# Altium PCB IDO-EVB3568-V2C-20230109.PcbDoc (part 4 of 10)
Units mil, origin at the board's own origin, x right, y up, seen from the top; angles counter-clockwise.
Board outline 5318 x 3544 mil, 2 copper layers (TOP, BOTTOM), stack 6.8 mil thick; 790 components, 626 nets, 2890 pads, 1922 vias.
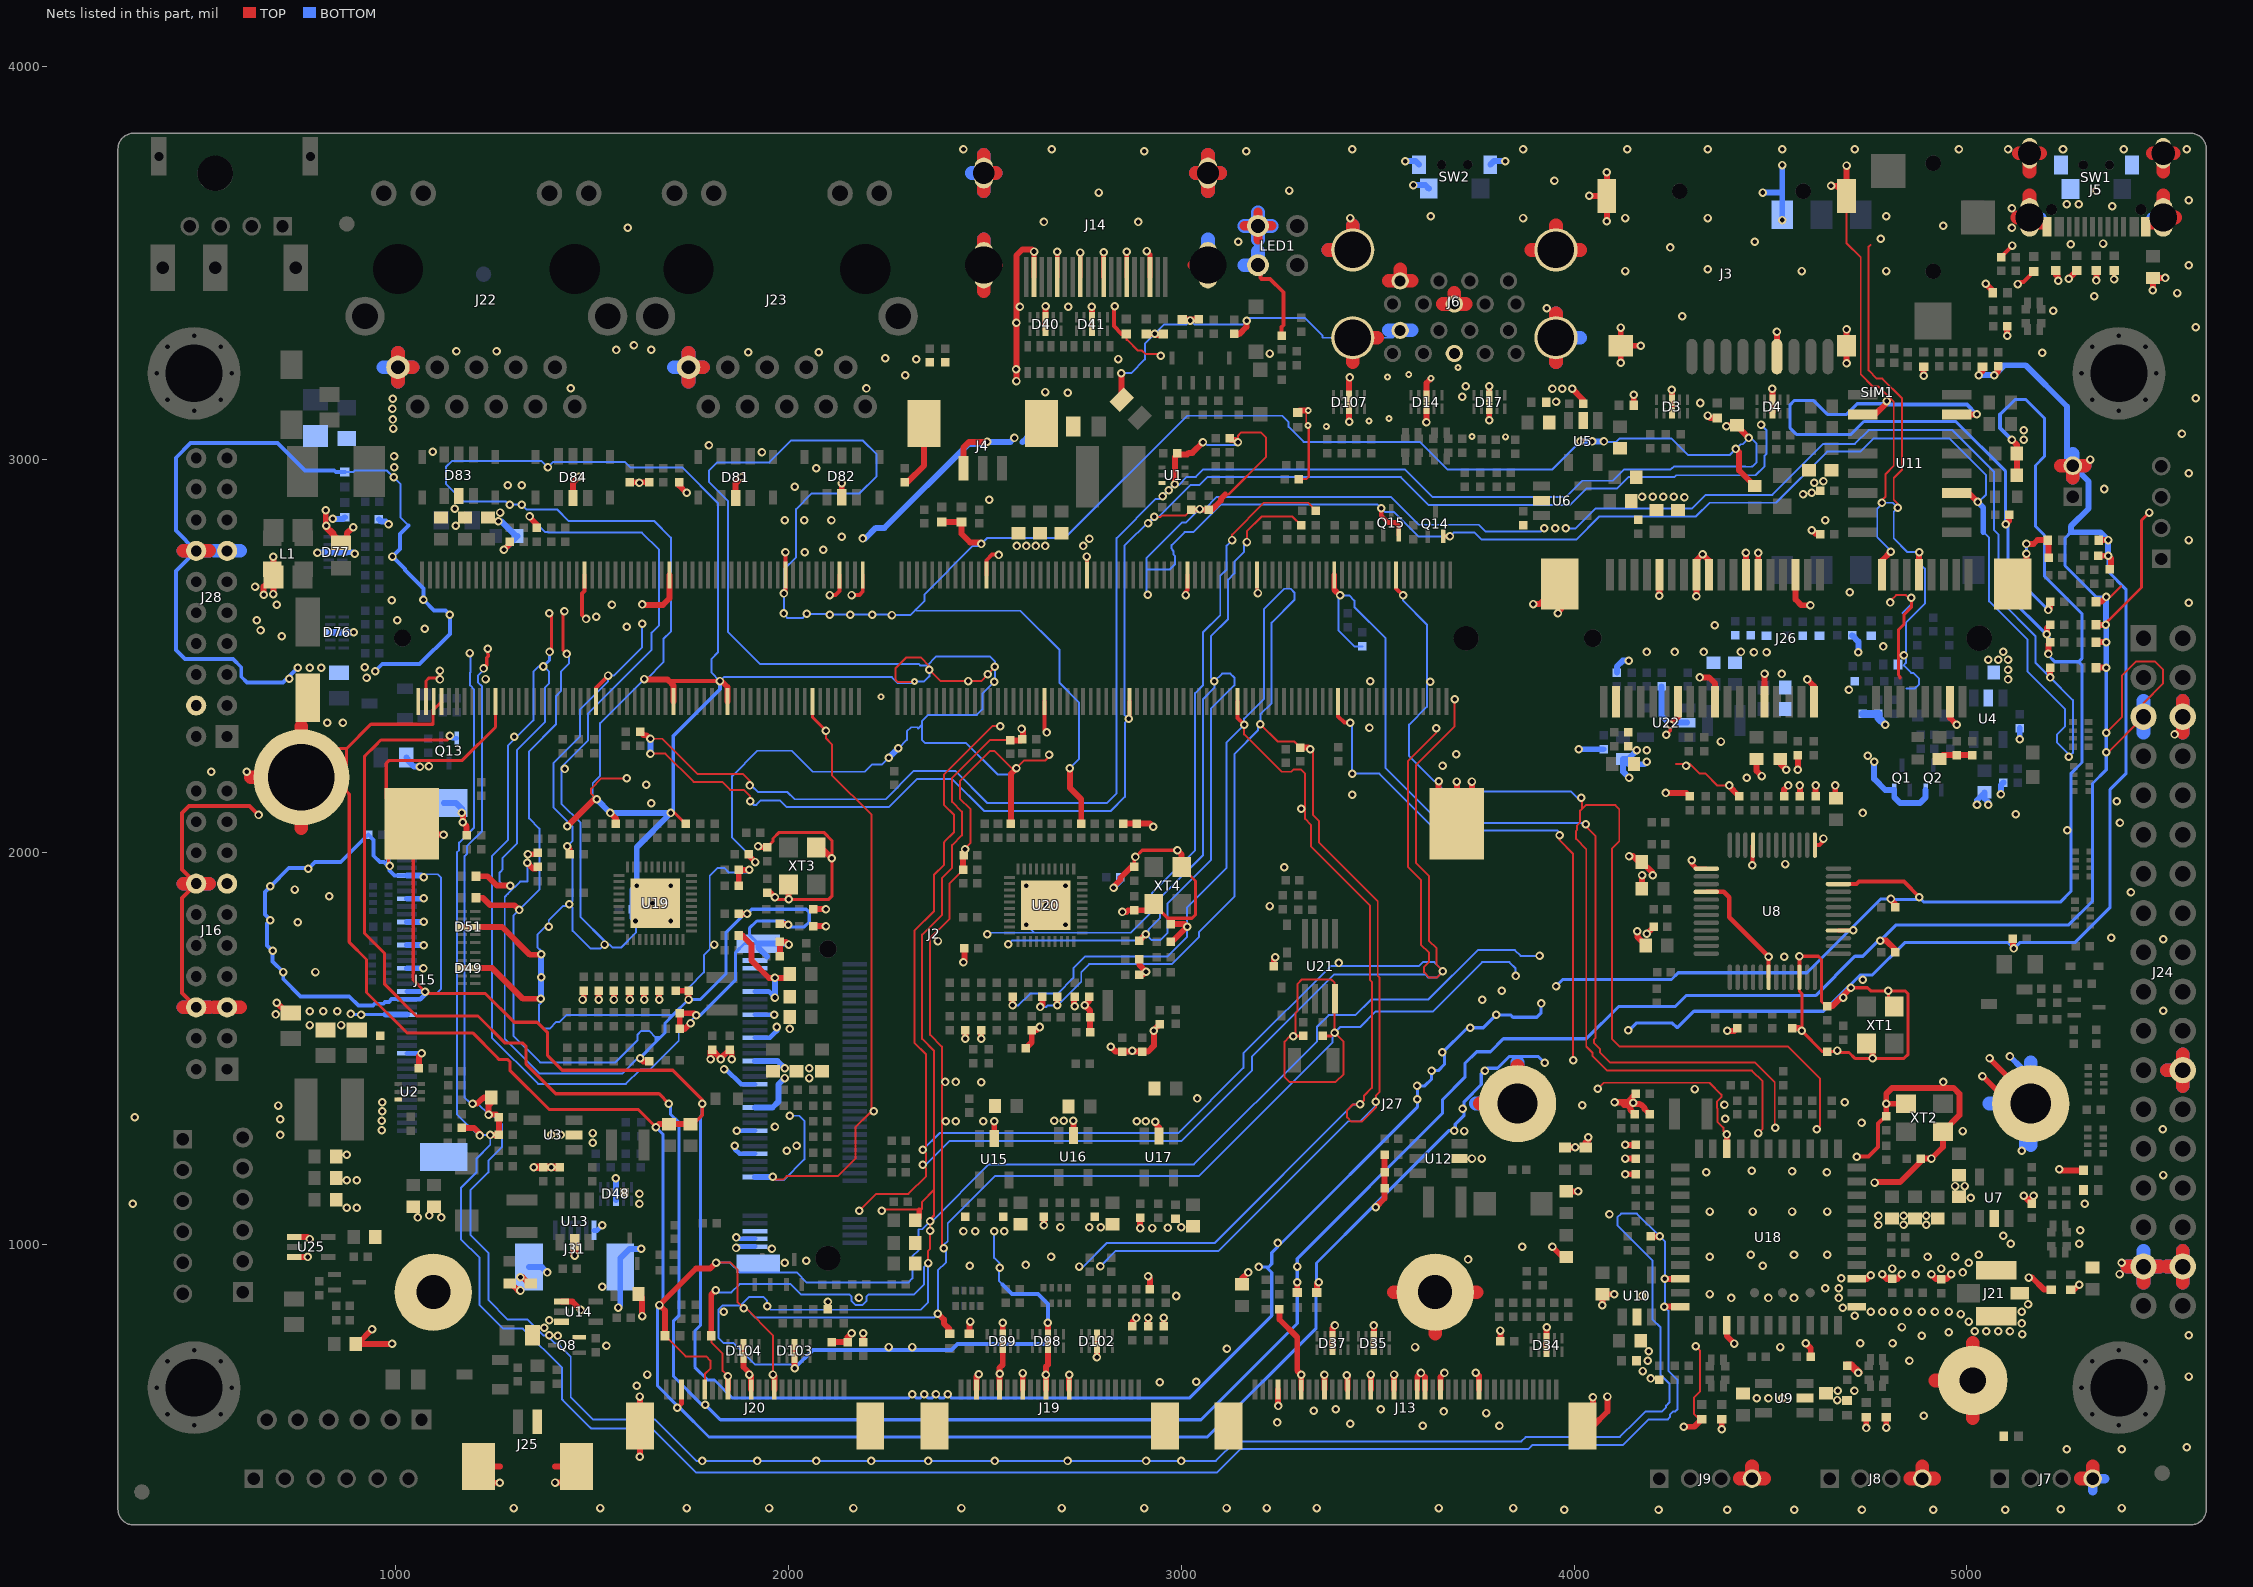
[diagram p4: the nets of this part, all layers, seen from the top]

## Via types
v1: diameter 21.65, hole 11.81, TOP to BOTTOM, 1878 vias
v2: diameter 17.72, hole 7.87, TOP to BOTTOM, 44 vias

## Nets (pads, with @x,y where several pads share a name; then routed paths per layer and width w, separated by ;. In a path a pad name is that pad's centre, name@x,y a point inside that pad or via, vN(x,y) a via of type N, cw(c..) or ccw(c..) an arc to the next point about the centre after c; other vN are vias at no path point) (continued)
GND: C3.2 C4.1 C5.1 C6.1 C7.1 C9.1 C10.1 C11.1 C12.1 C14.1 C15.1 C16.1 C18.1 C19.1 C20.1 C21.1 C22.1 C23.1 C25.1 C26.1 C27.1 C28.1 C29.1 C30.1 C31.1 C32.1 C33.2 C34.2 C35.1 C36.2 C37.2 C38.2 C40.2 C42.2 C43.2 C44.1 C45.1 C46.2 C47.2 C48.1 C49.1 C50.1 C51.1 C52.2 C53.2 C54.1 C55.1 C56.1 C57.1 C58.1 C59.1 C60.1 C61.1 C62.1 C63.2 C65.1 C66.1 C67.1 C68.1 C71.1 C73.2 C74.2 C76.2 C77.2 C78.1 C79.1 C80.1 C81.1 C82.1 C83.1 C84.1 C85.1 C86.1 C87.1 C88.1 C89.1 C90.1 C91.1 C93.1 C94.1 C95.1 C96.1 C97.1 C98.1 C99.1 C100.1 C101.1 C102.1 C103.1 C104.1 C105.1 C106.1 C107.1 C109.1 C110.1 C111.1 C112.1 C114.2 C115.1 C116.1 C117.1 C118.1 C119.1 C120.1 C121.1 C122.1 C123.1 C125.1 C126.1 C127.1 C128.1 C129.1 C130.1 C131.1 C132.1 C133.1 C134.1 C135.1 C136.1 C137.1 C138.1 C139.1 C140.1 C141.1 C142.1 C143.1 C144.1 C145.1 C146.1 C147.1 C148.1 C149.1 C150.1 C151.1 C152.1 C153.1 C154.1 C155.1 C156.1 C157.1 C158.1 C159.1 C160.1 C161.1 C162.1 C163.1 C164.2 C165.1 C166.1 C167.1 C168.2 C169.1 C170.1 C171.1 C172.1 C173.1 C174.1 C175.1 C176.2 C177.2 C179.1 C180.1 C181.1 C182.1 C183.2 C184.2 C185.2 C186.2 C188.2 C190.1 C191.1 C192.1 C193.1 C194.1 C195.1 C196.1 C197.1 C198.1 C199.1 C200.1 C201.1 C202.1 C203.1 C204.1 C205.1 C206.1 C208.1 C209.1 C214.1 C215.1 C216.1 C217.1 C218.1 C219.1 C220.1 C221.1 C222.1 C243.1 C244.1 C245.1 C247.1 C248.1 C249.1 C250.1 C251.1 C252.1 C253.1 C254.1 C255.1 C258.1 C259.1 C260.1 C261.1 D2.1 D3.3 D3.8 D4.3 D4.8 D5.1 D6.1 D7.1 D8.1 D9.1 D10.1 D12.1 D14.3 D14.8 D15.2 D16.2 D17.3 D17.8 D18.1 D19.1 D20.1 D21.1 D22.1 D23.1 D24.1 D25.1 D26.1 D27.1 D28.1 D29.1 D30.1 D31.1 D32.1 D33.1 D34.3 D34.8 D35.3 D35.8 D36.2 D37.3 D37.8 D38.2 D40.3 D40.8 D41.3 D41.8 D44.2 D45.2 D46.2 D47.2 D48.3 D48.8 D49.3 D49.8 D51.3 D51.8 D52.2 D53.2 D64.2 D65.2 D71.2 D72.2 D73.2 D74.2 D75.2 D76.3 D76.8 D77.3 D77.8 D79.2 D80.2 D81.2 D82.2 D83.2 D84.2 D96.2 D97.1 D98.3 D98.8 D99.3 D99.8 D100.2 D101.2 D102.3 D102.8 D103.3 D103.8 D104.3 D104.8 D105.2 D106.2 D107.3 D107.8 H1.1 H2.1 J2.15 J2.30 J2.31 J2.51 J2.56 J2.69 J2.84 J2.95 J2.106 J2.121 J2.145 J2.151 J2.158 J2.165 J2.180 J2.194 J2.195 J2.214 J2.217 J2.240 J2.254 J2.256 J2.258 J2.260 J2.N1 J2.N2 J2.N3 J2.N4 J3.6 J3.10 J3.11 J3.12 J3.13 J4.3 J4.4 J4.5 J5.A1 J5.A12 J5.B1 J5.B12 J5.H1 J5.H2 J5.H3 J5.H4 J6.4 J6.7 J6.13 J6.16 J6.19 J6.20 J6.21 J6.22 J7.4 J8.4 J9.4 J11.2 J13.11 J13.16 J13.18 J13.19 J13.22 J13.25 J13.28 J13.31 J13.34 J13.37 J13.41 J13.42 J14.2 J14.5 J14.8 J14.11 J14.14 J14.17 J14.20 J14.21 J14.22 J14.23 J15.11 J15.16 J15.18 J15.19 J15.22 J15.25 J15.28 J15.31 J15.34 J15.37 J15.41 J15.42 J16.5 J16.6 J16.13 J16.14 J19.10 J19.13 J19.16 J19.19 J19.22 J19.25 J19.26 J20.10 J20.13 J20.16 J20.19 J20.22 J20.25 J20.26 J21.1 J21.3 J21.4 J22.10 J23.10 J24.5 J24.6 J24.24 J24.33 J24.34 J25.2 J25.3 J25.4 J26.4 J26.9 J26.15 J26.18 J26.21 J26.26 J26.27 J26.29 J26.34 J26.35 J26.37 J26.40 J26.43 J26.50 J26.55 J26.56 J27.1 J27.3 J27.9 J27.15 J27.21 J27.27 J27.33 J27.39 J27.45 J27.51 J27.57 J27.71 J27.73 J27.75 J27.G1 J27.G2 J27.G3 J27.G4 J28.4 J28.13 J28.14 J31.6 J31.7 J31.8 L1.3 LED1.2 LED1.4 Q1.2 Q2.2 Q8.2 Q13.2 Q14.2 Q15.2 R2.2 R5.1 R6.1 R9.1 R12.1 R16.1 R28.1 R33.1 R36.1 R41.1 R45.1 R51.1 R60.1 R72.1 R73.2 R79.1 R81.2 R100.1 R101.1 R102.1 R108.1 R118.1 R119.1 R120.1 R173.1 R176.1 R179.1 R201.2 R208.1 R213.2 R219.1 R225.1 R229.1 R233.1 R235.1 R237.1 R239.1 R241.1 R242.1 R245.1 R268.2 R271.1 R273.1 R277.1 R281.1 R284.1 R286.1 R287.1 R289.1 R290.1 R293.1 R345.1 R385.2 R419.1 R421.1 SIM1.C5 SW1.1 SW1.2 SW1.4 SW2.1 SW2.2 SW2.4 U1.3 U2.3 U3.2 U4.2 U5.2 U6.2 U7.2 U8.6 U8.10 U8.16 U8.22 U8.25 U8.33 U8.37 U8.40 U9.2 U10.2 U11.2 U11.11 U11.15 U12.2 U13.2 U14.1 U14.3 U15.2 U16.2 U17.2 U18.1 U18.3 U18.20 U18.31 U18.33 U18.36 U19.41 U20.41 U21.4 U22.2 U25.1 U25.3 XT1.2 XT1.4 XT2.2 XT2.4 XT3.2 XT3.4 XT4.2 XT4.4 | length 160023.3
  TOP w5: v1(1511,2135) 1497,2149 1497,2162 1523,2188 v1(1588,2188) ; v1(1648,2251) 1686,2251 1758,2179 1831,2179 1851,2159 1886,2159 1902,2143 v1(1902,2130) ; v1(1648,2289) 1678,2289 1768,2199 1884,2199 1901,2182 v1(1901,2170) ; D106.2@1685.1,769 1737.78,716.33 1789.59,716.33 1800.33,705.59 1800.33,685.33 1786.34,671.34 J20.19@1786.34,632.01 ; D105.2@1802.9,769 1802.9,752.1 1832,723 1832,679.39 v1(1845.39,666) ; v1(1815,955) 1852,955 1870,937 1870,854 v1(1885.5,838.5) 1891.5,838.5 1960,770 v1(1960,670) ; v1(1958.99,1173.99) 1958.99,1172.99 1964.98,1167 1987,1167 1995,1175 2125,1175 2170,1220 2170,1300 2204.5,1334.5 ; v1(2095,2309) 2095,2290 2110,2275 2110,2196 2211,2095 v1@2211,1346 ; v1(2180,1087) 2223,1130 2305,1130 2350,1175 2350,1195 v1(2341,1204) 2350,1213 2350,1233 v1(2341,1242) 2350,1251 2350,1485 2320,1515 2320,1800 2370,1850 2370,1942.43 2395.95,1968.38 2395.95,1983.38 2396,1983.43 2396,2025.14 2396.33,2025.47 2396.33,2026.41 2421,2051.08 2421,2095.21 2396,2120.21 2396,2198.14 2518.86,2321 v1(2539,2321) ; v1(2237,1087) 2240,1090 2327.5,1090 2332.5,1085 2340,1092.5 2340,1110 2370,1140 ; v2(2320,2435) 2318,2433 2278,2433 2272,2439 2272,2468 2300,2496 2336,2496 2358,2474 v1(2358,2465) 2387,2436 v1(2457,2436) 2490,2436 v1(2507,2453) 2525,2471 v1(2525,2472) ; v1(2355,954) v1@2355,955 ; v1@2360,960 v1@2355,955 ; v1(2395,992) 2390,997 2390,1406 v1(2399,1415) 2390,1424 2390,1505 2360,1535 2360,1780 2360.81,1780.81 2360.81,1781.67 2410,1830.86 2410,1920.72 C167.1@2444.28,1955 ; v1(2449,2008) 2451,2010 2451,2012 2462.5,2023.5 2462.5,2110.28 2436,2136.78 2436,2181 2513,2258 2524,2258 2568,2214 v1(2580,2214) 2599.95,2233.95 2653.95,2233.95 2663,2243 v1(2663,2248) v1@2662,2248 ; C97.1@2564,2285.72 2512.43,2285.72 2416,2189.29 2416,2128.49 2441,2103.49 2441,2042.79 2416.33,2018.12 2416.33,2017.18 2416,2016.86 2416,1975.14 2415.95,1975.1 2415.95,1960.1 2390,1934.14 2390,1840 2340,1790 2340,1525 2370,1495 2370,1140 ; D44.2@2860,3320.1 2860,3305 2861.86,3305 2889.53,3277.33 2899.67,3277.33 2908,3269 2942,3269 v1(2947,3264) ; v1(2931,2854) 2947,2854 2951,2858 3010.72,2858 C12.1@3025,2872.28 ; 3111.72,2911 3120,2911 3215.67,3006.67 3215.67,3055.65 3202.32,3069 3153,3069 3144,3060 v1(3144,3044) ; v1(3129,2795) 3129,2809 3210,2890 3322.72,2890 C159.1@3342.72,2870 ; v1(3160,2325) 3160,2300.14 3255.14,2205 3280,2205 3286,2211 3304,2211 3315,2200 3315,2085 3330,2070 3330,2015 3480,1865 3480,1675 3485,1670 3485,1400 3465,1380 3465,1368 v1(3455,1358) 3437,1358 3422,1343 3422,1325 3433,1314 3459,1314 3495,1350 v1(3495,1365) 3495,1380 3505,1390 3505,1680 3500,1685 3500,1875 3350,2025 3350,2080 3335,2095 3335,2255.44 v1(3327.72,2262.72) ; v1(3167,2790) 3167,2817 3205,2855 3282.72,2855 C158.1@3305,2832.72 ; v1(3201,2326) 3245,2282 3287.72,2282 C95.1@3303,2266.72 ; C259.1@3298.72,2950 3318.05,2950 3324,2955.95 ; v2(3323,3125) 3318,3120 3318,3091 3322,3087 v2(3322.06,3087) 3322.06,3086.94 v2@3324,3085 ; U21.4@3390,1625.93 v1(3390,1540) 3413,1517 3413,1435 3393,1415 3275,1415 3263,1427 3263,1518 3275,1530 3284,1530 v1(3285,1531) 3290,1536 3290,1590 3296,1596 3296,1665 3307,1676 3382,1676 3390,1668 3390,1630.9 3391.39,1629.51 U21.4@3391.39,1627.32 ; v1(3649,2316) 3649,2304 3577.63,2232.63 3577.63,1962.37 3610,1930 3610,1765 3630,1745 3630,1720 3618,1708 3618,1694 3631,1681 3650,1681 v1(3666,1697) 3666,1698 3650,1714 3650,1755 3630,1775 3630,1940 3597.63,1972.37 3597.63,2222.63 3696,2321 v1(3696,2390) ; v1(3963,2043) 3963,2030.86 3997,1996.86 3997,1471 v1(3998,1470) ; v1(4018,2139) 4020,2137 4020,2110 ; v1(4029.5,2071.5) 4034,2067 4034,2062 4054,2042 4054,1534.71 4054,1526.43 4051,1523.43 4051,1513.63 4066.33,1498.31 4066.33,1489.82 4091.14,1465 4123.15,1465 4460.01,1464.99 4511,1414 4511,1299 v1(4512,1298) ; v1(4060,1398) 4075,1413 4344.86,1413 4374.99,1382.86 4374.99,1376.33 4363.67,1365.01 4363.67,1348.99 4365.67,1346.99 4365.67,1312.99 4380,1298.67 4380,1290 v1(4388.7,1281.3) ; 4260,2225 4295,2225 4320,2200 4335,2200 4365,2170 v1(4395,2170) ; v1(4310,742) 4321,731 4321,627 4305,611 4305,570 4318.9,556.1 D25.1@4325,556.1 ; v1(4469,1285) 4480,1296 4480,1416.71 4452.71,1444 4083.86,1444 4046.33,1481.53 4046.33,1490.02 4031,1505.35 4031,2008 4005,2034 4005,2054 4007,2056 4007,2067.33 4015,2075.33 4015,2105 4020,2110 ; v1(4618,1295) 4626,1303 4626,1424 4545,1505 4116.21,1505 4096,1525.21 4096,2009 4115,2028 4115,2110 4105,2120 4030,2120 4020,2110 ; J3.12@4693.7,3671.57 4693.7,3551.3 4730,3515 4730,3217 4761,3186 4775,3186 4814,3147 4814,2984 4793,2963 4793,2905 4784,2896 v1(4784,2890) ; 4755,3547 4750,3542 4750,3227 4771,3206 4785,3206 4835,3156 4835,2974 4814,2953 4814,2898 4824,2888 v1(4824,2877) ; v1(4805,2636) 4805,2640 4820,2655 4845,2655 4852,2648 v1(4859,2648) ; v1(5355,2255) 5360,2255 J24.5@5450,2345 5450,2380 5500,2430 5500,2465 5479,2486 5431,2486 5395,2450 5395,2344 v1(5355,2304) ; v1(5355,2650) 5365,2650 5393,2678 ; 2204.5,1334.5 2211.5,1334.5 v1(2217,1340) v1@2211,1346 ; 2204.5,1334.5 2211,1341 v1@2211,1346 ; v1@2355,955 2355,985 2360,990 v1(2360,1036) v1(2360,1060) 2360,1065 2370,1075 2370,1140
  TOP w6: 3324,2955.95 v2@3324,3085
  TOP w8: H2.1@759,2191 810.41,2242.41 827.21,2242.41 848.8,2264 874,2264 ; v1(984,1965) 981.26,1967.74 981.26,1991.55 977,1995.81 977,2009.6 J2.N2@1039.96,2072.56 975.17,2137.35 975.17,2226.17 983,2234 1169,2234 1253.54,2318.54 J2.240@1253.54,2383.58 ; J2.N2@1044,2068.52 1044,1675 v1(1074,1645) 1079,1640 1228,1640 1301.02,1566.98 1359.41,1566.98 1386,1540.39 1386,1482.16 1422.27,1445.9 1423,1445.9 1423,1445 1705,1445 1780,1370 v1(1780,1360) 1776,1356 1780,1352 1780,1330 1757.56,1307.56 C25.1@1750,1307.56 ; J2.258@1076.37,2383.58 1076.37,2436 1084.37,2444 1108,2444 v1(1112,2440) v1(1112,2462) ; J2.254@1115.74,2383.58 1094,2361.84 1094,2326 936,2326 874,2264 ; v1(1137.41,2296.22) 1137.41,2292.41 1131,2286 1004.54,2286 961.46,2286 945.84,2270.38 923,2247.54 920,2244.54 920,1793 970.93,1742.07 970.93,1663.92 1051.85,1583 1209,1583 1278,1514 1323,1514 1331.5,1505.5 1331.5,1460.5 1407,1385 1670,1385 v1(1695,1360) ; v1(1223,2468) 1231,2476 1231,2483.26 1231.17,2483.44 1231.17,2495.21 1235.06,2499.1 1235.06,2503.75 1233.06,2505.74 1233.06,2517.06 v1(1234,2518) ; 1255.17,1479.83 1195,1540 1028,1540 925,1643 925,1727 881,1771 881,2147.88 874,2154.88 874,2264 ; 1255.21,1479.83 1263.04,1472 1285,1472 1290,1467 1290,1445 1390,1345 1617,1345 v1(1662,1300) ; v1(1390,2609) 1395.66,2603.34 1395.66,2514.66 v1(1391,2510) ; v1(1429,2614) 1425,2610 1425,2515 v1(1435,2505) ; v1(1700,2100) 1710,2100 1737.28,2072.72 C141.1@1738,2072.72 ; C129.1@1945,2012.72 1959.99,2027.71 1959.99,2034.99 1975.66,2050.66 2089.34,2050.66 2110,2030 v1(2110,1985) 2110,1888 2102,1880 v1(2000,1880) 1970,1880 v1(1965,1885) ; J2.158@2060.63,2383.58 2060.63,2343.37 v1(2095,2309) ; C154.1@2880,1962.72 2880,1985 v1(2883,1988) 2900,2005 v1(2990,2005) ; XT4.2@2929.57,1867.76 2965.32,1832 3027,1832 3036,1841 3036,1926.68 XT4.4@3000.43,1962.24 ; J2.51@3192.52,2706.42 3192.52,2662.48 v1(3195,2660) ; v1(3285,1531) 3286,1531 3287.28,1532.28 C179.1@3310,1532.28 ; C180.1@3360,1532.28 3382.28,1532.28 v1(3390,1540) ; U21.4@3390,1625.93 U21.4@3390,1630.9 ; v1(4235,2299) 4245,2309 v1(4245,2325) ; U8.10@4573.9,1681.7 4573.9,1646.1 4580,1640 v1(4580,1545) 4632.72,1492.28 C51.1@4645,1492.28 4667.28,1492.28 v1(4670,1495) 4675,1490 4700,1490 4715,1475 v1@4759.57,1475 ; v1(4573.9,1735) 4622,1735 4630,1727 4630,1620 4642.28,1607.72 C49.1@4645,1607.72 ; v1(4705,1655) 4747,1655 4755,1647 v1(4800.43,1647) ; v1(4760,1475) 4840,1475 4850.66,1485.66 4850.66,1639 4842.66,1647 v1(4800.43,1647) ; XT1.4@4815.43,1607.24 4800.43,1622.24 v1(4800.43,1647) ; 4830,2444 4830,2447 4826,2451 4826,2567 4840,2581 4840,2605 4859,2624 v1(4859,2648) ; v1(5354,2579) 5354,2583.61 5360.39,2590 5360.77,2590 5445,2674.23 5445,2845 v1(5465,2865)
  TOP w10: J16.6@491.26,1605.08 455,1641.34 455,1883.78 J16.14@491.26,1920.04 455,1956.3 455,2100 473,2118 627,2118 v1(650,2095) ; J2.N2@1039.96,2072.56 J2.N2@1044,2068.52 ; J2.217@1479.92,2706.42 1479.92,2664.92 1474,2659 1474,2604 v1(1484,2594) ; J2.214@1509.44,2383.58 1509.44,2418.44 1540,2449 v1(1540,2450) ; 1695.29,2436 v1(1825,2436) ; v1(1988,2659) 1991.73,2662.73 J2.165@1991.73,2706.42 v1(1991.73,2764) ; v1(2105,2655) 2119.52,2655 2129.52,2665 J2.151@2129.52,2706.42 ; v1(2160,2655) 2180,2655 2188.58,2663.58 J2.145@2188.58,2706.42 ; J2.121@2503.54,2706.42 2503.54,2743.54 2517.93,2757.93 2532.07,2757.93 2533,2757 v1(2535,2757) ; J2.106@2651.18,2383.58 2651.18,2310.82 v1(2657,2305) ; J2.95@2759.44,2706.42 v1(2759.44,2753) ; v1(2830,3390) 2828,3388 2828,3340.1 2848,3320.1 D44.2@2860,3320.1 ; v1(2865.71,2339.71) 2867.71,2341.71 J2.84@2867.71,2383.58 ; v1(3011,2655) 3011,2663 3015.35,2667.35 J2.69@3015.35,2706.42 ; J2.56@3143.3,2383.58 3143.3,2341.7 v1(3160,2325) ; LED1.4@3195,3495 3201,3489 3201,3463 3204,3460 3226,3460 3260,3426 3260,3342 3255,3337 R9.1@3255,3315.72 ; J2.30@3399.21,2383.58 3399.21,2345.79 3415,2330 v1(3430,2330) ; J2.15@3546.85,2706.42 3546.85,2672.15 v1(3564.5,2654.5) ; v1(4454,1967) 4454,2016.5 U8.33@4455.8,2018.3 ; U8.6@4495.2,1681.7 v1(4495.2,1734) ; U8.10@4573.9,1681.7 v1(4573.9,1735) ; U8.25@4613.3,2018.3 4625,2018.3 4635,2028.3 v1(4635,2035) ; U8.16@4673.3,1800.8 4709.8,1800.8 v1(4710.8,1801.8) ; U8.22@4673.3,1918.9 4718.9,1918.9 4725,1925 4840,1925 4879,1886 v1(4879,1885) ; v1(4720,1225) 4750,1225 4774,1249 4774,1309 4792.72,1327.72 C117.1@4795,1327.72 ; R28.1@5088,3515.72 5088,3517 v1(5116,3545) ; v1(5130,3447) 5135,3452 5143.9,3452 D7.1@5171,3479.1 ; v1(5375,3459) D8.1@5375,3481.1
  TOP w12: v1(1716.5,585.5) 1727.28,596.28 J20.22@1727.28,632.01 ; J14.2@2624.69,3465 v1(2624.69,3529.69) ; J14.5@2683.74,3465 v1(2683.74,3528.74) ; J14.8@2742.8,3465 v1(2742.8,3527.2) ; J14.11@2801.85,3465 v1(2801.85,3528.15) ; J14.14@2860.91,3465 v1(2860.91,3529.09) ; v1(2912,3531) 2919.96,3523.04 J14.17@2919.96,3465 ; v1(3509,2876) 3509,2857 3526.5,2839.5 3545.2,2839.5 3553.68,2831.01 Q15.2@3553.68,2807.5 ; Q14.2@3666.68,2804.5 v1(3684,2804.5) ; v1(4300,1980) 4300,1970.3 4312,1958.3 U8.37@4336.7,1958.3 ; U8.40@4336.7,1899.2 4380.8,1899.2 4395,1885 4395,1834.2 v1(4495.2,1734)
  TOP w15: v1(663,2656) 663,2676.35 L1.3@687.6,2700.95 ; v1(687.6,2657.6) L1.3@687.6,2700.95 ; v1(687.6,2752.4) L1.3@687.6,2700.95 ; v1(696,1617) 722.52,1590.48 C93.1@732,1590.48 ; U25.3@740.53,969.41 v1(775,969.41) ; U25.1@740.53,1020.6 774.4,1020.6 v1(780,1015) ; v1(821,2871) 821,2827.48 C4.1@860,2788.48 ; v1(822,2831) 841,2812 841,2809 860,2790 C4.1@860,2788.48 ; v1(891,2828) 875,2812 875,2803.48 C4.1@860,2788.48 ; C243.1@897.56,748 C243.1@902,748 ; v1(939,785) C243.1@902,748 ; v1(990,748) C243.1@902,748 ; J2.N2@1039.96,2072.56 1047.44,2072.56 1075,2045 v1(1121,2045) ; C258.1@1058.28,1450 1058.28,1481.27 v1(1065,1487.99) ; v1(1167,2101) 1170.39,2097.61 1170.39,2076.39 v1(1170,2076) 1180,2066 C90.1@1180,2042.72 ; R12.1@1167.72,1298 1199,1298 1215.67,1281.33 1215.67,1281.09 v1(1213.37,1278.79) ; D49.8@1169.44,1705 D49.3@1200.56,1705 1245,1705 1323,1627 v1(1369,1627) ; D51.8@1169.44,1810 D51.3@1200.56,1810 1270,1810 1341,1739 1368.5,1739 v1(1369.5,1740) ; v1(1195,1360) 1206.6,1360 1218.92,1372.33 1221.33,1372.33 1224,1375 C22.1@1242.44,1375 1242.44,1361.44 1236,1355 1236,1332.37 v1(1235.63,1332) 1255.28,1332 C23.1@1262.28,1325 R16.1@1262.28,1280 v1(1240,1280) ; D52.2@1203.9,1884 1221,1884 1240,1865 1302,1865 v1(1314,1853) ; D53.2@1203.9,1939 1233,1939 1257,1915 v1(1291,1915) ; J25.3@1225,480 1210,465 J25.3@1210,435.83 ; v1(1264.39,394.39) 1220.61,394.39 1210,405 J25.3@1210,435.83 ; 1265,435.83 J25.3@1210,435.83 ; v1(1275,2770) 1290,2785 C135.1@1290,2791.28 ; R119.1@1290,901.46 1293.54,901.46 1311,884 v1(1317,884) ; v1(1317,918) 1322,918 1338.54,901.46 R120.1@1343,901.46 ; v1(1334,1973) 1349,1958 1356.28,1958 C143.1@1361.28,1963 ; v1(1336,1995) 1357.28,1995 C148.1@1361.28,1999 ; v1(1340,2855) 1340,2853 1359,2834 C134.1@1359,2826.72 ; v1(1405,395) 1440,395 1460,415 J25.4@1460,435.83 1405,435.83 ; U14.1@1421.69,855.59 1449.41,855.59 v1(1470.5,834.5) ; v1(1436,2015) 1442.28,2008.72 C150.1@1442.28,1995 ; v1(1436,2066) 1505,2135 v1(1511,2135) ; D84.2@1451,2901.85 1451,2942 v1(1465,2956) ; v1(1475,1625) 1478,1628 R245.1@1478,1647.28 ; v1(1516,1625) R242.1@1516,1647.28 ; v1(1546,2100) 1560,2086 C140.1@1560,2072.72 ; v1(1555,1625) R239.1@1555,1647.28 ; v1(1595,1625) R235.1@1595,1647.28 ; C142.1@1595,2942.28 1619,2942.28 v1(1620,2941.28) 1621,2942.28 R213.2@1645,2942.28 ; C94.1@1617.56,875 1626,866.56 1626,820 v1(1627,819) ; v1(1620.98,460.99) J20.26@1620.98,538.5 v1(1620.98,614.01) ; v1(1622,1475) 1629.72,1467.28 C147.1@1645,1467.28 ; C30.1@1622,2306.72 1630.72,2298 1638,2298 1647,2289 v1(1648,2289) ; v1(1627,2631) 1628,2630 1680,2630 1696.45,2646.45 J2.195@1696.45,2706.42 ; v1(1632,1625) R237.1@1632,1647.28 ; v1(1632,2441) 1633,2440 1691.29,2440 1695.29,2436 1706.29,2425 J2.194@1706.29,2383.58 ; v1(1662,1300) 1669.56,1307.56 C21.1@1695,1307.56 C25.1@1750,1307.56 ; v1(1670,1625) C146.1@1670,1647.28 ; D106.2@1685.1,769 1685.1,832.9 v1(1671,847) 1764,940 1800,940 v1(1815,955) ; C151.1@1712,1647.28 C152.1@1745,1647.28 v1(1745,1625) ; C156.1@1721,2942.28 1721,2934 v1(1740,2915) ; v1(1750,1565) 1735,1550 C144.1@1722.72,1550 C145.1@1722.72,1590 1760,1590 v1(1765,1585) ; v1(1801,1473) 1801,1493.28 C137.1@1805,1497.28 1824,1478.28 1824,1476 v1@1826,1474 ; D105.2@1802.9,769 1802.9,873.9 v1(1814,885) ; v1(1825,2436) 1829.09,2436 1844.09,2421 J2.180@1844.09,2383.58 ; v1(1827,1473) v1@1826,1474 ; J20.16@1845.39,632.01 v1(1845.39,666) ; v1(1855,1473) 1855,1492.28 C136.1@1850,1497.28 1849.28,1497.28 v1@1826,1474 ; D81.2@1865,2901.85 1865,2940 v1(1880,2955) ; R225.1@1872.72,1788 1882,1788 1905,1765 1905,1725 1950,1680 v1(1965,1680) 1992.44,1680 C217.1@2002.44,1690 ; R229.1@1872.72,1843 1893,1843 v1(1894,1843) ; C139.1@1872.72,1915 R241.1@1872.72,1955 v1(1900,1955) ; D104.3@1885,745.56 D104.8@1885,714.44 1885,689 1900,674 v1(1900,670) 1904.45,665.55 J20.13@1904.45,632.01 ; C149.1@1897.72,1995 1897.72,1992.28 v1(1915,1975) ; v1(1922,2015) 1924.28,2012.72 C129.1@1945,2012.72 ; C130.1@1945,1897.28 1952.72,1897.28 v1(1965,1885) ; v1(1960,670) 1963.51,666.5 J20.10@1963.51,632.01 ; R233.1@1977.72,1735 C133.1@1977.72,1772 1993,1772 v1(2000,1765) ; C132.1@1977.72,1818 1996,1818 v1(1999,1815) ; XT3.2@1999.57,1917.76 1999.57,1880.43 v1(2000,1880) ; v1(2015,686) D103.8@2015,714.44 D103.3@2015,745.56 ; C131.1@2062.72,1812 v1(2095,1812) ; R219.1@2062.72,1855 v1(2095,1855) ; XT3.4@2070.43,2012.24 2082.76,2012.24 v1(2110,1985) ; C99.1@2100,835.72 v1(2100,855) ; C104.1@2110,752.72 C100.1@2150,752.72 2150,765 v1(2160,775) ; D82.2@2135,2903.85 v1(2135,2940) ; C98.1@2190,752.72 v1(2190,775) ; C166.1@2295,2942.28 2302.28,2942.28 2344.39,2984.39 J4.5@2344.39,3092.17 2344.39,3095.61 J4.5@2326,3114 ; C216.1@2322.56,1060 2332.5,1069.94 2332.5,1085 2332.5,1087.5 ; v1(2380,825) 2395,810 2395,800 2410,785 D101.2@2410,773.9 ; D6.1@2390,2841.1 D5.1@2440,2841.1 2440,2811 2462,2789 2486,2789 v1(2490,2785) ; C167.1@2444.28,1955 2444.28,1991 C174.1@2445.28,1992 2445.74,1992.46 2445.74,2004.74 v1(2449,2008) ; J4.3@2444.79,2978 2444.79,3030 2459.79,3045 v1(2505,3045) ; v1(2445,1720) 2447.28,1722.28 C162.1@2447.28,1755 ; v1(2450,1525) R293.1@2450,1547.28 ; D100.2@2460,773.9 2460,803 v1(2462,805) ; J19.22@2477.99,632.01 2477.99,664.99 v1(2484,671) ; v1(2490,1525) R290.1@2490,1547.28 ; U15.2@2523.57,1271.37 v1(2523.57,1315) ; J19.19@2537.05,632.01 v1(2537.05,672.05) 2537.05,687.05 2545,695 D99.8@2545,739.44 D99.3@2545,770.56 v1(2545,802) ; C97.1@2564,2285.72 2565,2284.72 2592,2284.72 R421.1@2595,2287.72 2596.53,2289.25 2596.53,2310.47 v1(2593,2314) ; C165.1@2566,2072.72 2566,2200 v1(2580,2214) ; v1(2570,1610) R286.1@2570,1632.28 ; v1(2580,3200) v1(2580,3348) 2580,3520 2595,3535 2619.38,3535 v1(2624.69,3529.69) ; J19.16@2596.1,632.01 v1(2596.1,673.9) ; R287.1@2603.72,1501 2619,1516.28 C171.1@2619,1547.28 2631.28,1547.28 v1(2639,1555) ; v1(2641,1606) 2646,1611 R284.1@2646,1632.28 ; v1(2650,1050) R176.1@2650,1072.28 ; D40.3@2654,3329.44 D40.8@2654,3360.56 v1(2654,3390) ; J19.13@2655.16,632.01 v1(2655.16,669.84) 2655.16,690.16 2660,695 D98.8@2660,739.44 D98.3@2660,770.56 v1(2660,802) ; v1(2684,1610) C170.1@2684,1632.28 ; J19.10@2714.21,632.01 v1(2714.21,669.21) ; v1(2716,2214) 2716,2164 2745,2135 C164.2@2745,2072.72 ; U16.2@2725,1278.15 v1(2725,1316) ; v1(2728,1608) 2727,1609 2727,1631.28 C175.1@2728,1632.28 ; C176.2@2765,1632.28 2765,1621 v1(2754,1610) 2767.72,1596.28 C169.1@2767.72,1580 C168.2@2767.72,1542 ; D41.3@2772,3329.44 D41.8@2772,3360.56 v1(2772,3389) ; v1(2785,714) D102.8@2785,739.44 D102.3@2785,770.56 ; v1(2820,1505) 2832.72,1492.28 C161.1@2850,1492.28 2873,1492.28 v1(2875,1494.28) 2877,1492.28 C160.1@2900,1492.28 2915,1492.28 2930,1507.28 v1(2930,1545) 2930,1547.28 C172.1@2945,1562.28 ; v1(2827.22,1909.78) 2827.22,1912.22 2844.99,1929.99 2844.99,1934.99 2872.72,1962.72 C154.1@2880,1962.72 ; v1(2847,3220) 2847.75,3219.25 C6.1@2847.75,3152.08 ; v1(2850,1848) 2860,1848 2864.28,1852.28 C153.1@2880,1852.28 2914.09,1852.28 XT4.2@2929.57,1867.76 ; C173.1@2852,2072.72 R289.1@2886,2072.72 2920.28,2072.72 v1(2928,2065) ; C255.1@2875,792.72 2875,804 v1(2885,814) ; R273.1@2892.72,1688 2902,1688 v1(2910,1696) 2892.72,1713.28 R281.1@2892.72,1727 ; R277.1@2892.72,1775 2908.72,1791 v1(2909,1791) ; v1(2895,1043) R179.1@2895,1069.28 ; D45.2@2910,3320.1 2910.39,3319.71 2931.61,3319.71 v1(2932,3320.1) 2935,3317.1 2951,3317.1 D47.2@2954,3320.1 ; C254.1@2915,792.72 v1(2915,815) ; v1(2915,920) 2920,915 C96.1@2920,887.72 ; v1(2933,1314) 2933,1309.44 2942.72,1299.72 U17.2@2942.72,1277.09 ; C253.1@2955,792.72 v1(2955,815) ; R271.1@2972.72,1772 2976,1772 v1(3014.5,1810.5) 3008,1817 C155.1@2972.72,1817 ; v1(2983.5,2937.5) 2984,2938 2984,3006.28 2989.72,3012 C7.1@2989.72,3016 2992.72,3013 3015.05,3013 3019.05,3017 3028,3017 v1(3055,3044) ; v1(2990,2005) 3000.43,1994.57 XT4.4@3000.43,1962.24 ; D46.2@3002,3356.9 3020.1,3356.9 v1(3023,3354) 3025.72,3356.72 R108.1@3044,3356.72 ; C12.1@3025,2872.28 3044.28,2872.28 3046,2874 v1(3047,2874) 3048,2874 3049.72,2872.28 R5.1@3070,2872.28 3077.28,2872.28 3100.72,2895.72 3100.72,2900 3111.72,2911 ; R6.1@3122.72,3054 3126.72,3050 3138,3050 v1(3144,3044) ; C85.1@3134,3320.28 3145.72,3320.28 3147,3319 3166,3338 v1(3166,3353) ; C79.1@3154,899.56 3154,914 v1(3170,930) ; C181.1@3235.28,1710 3235.28,1729.28 v1(3239,1733) ; v1(3246.26,590) J13.37@3246.26,632.01 ; C80.1@3249.72,836 3249.72,810.28 3295,765 3295,680 v1(3305.32,669.68) J13.34@3305.32,632.01 ; D38.2@3295,878.9 v1(3295,905) ; D96.2@3296,3119.9 3301.1,3125 v2(3323,3125) ; C95.1@3303,2266.72 3323.72,2266.72 v1(3327.72,2262.72) ; D36.2@3345,878.9 3345,900 v1(3350,905) ; J13.31@3364.37,632.01 v1(3364.37,669.37) ; D37.8@3385,734.44 D37.3@3385,765.56 3385,789 v1(3391,795) ; J2.31@3389.37,2706.42 3389.37,2668.63 v1(3404,2654) ; v1(3421.43,668.43) 3423.43,666.43 J13.28@3423.43,632.01 ; v1(3427,3096) D107.3@3427,3130.44 ; D107.8@3427,3161.56 3427,3207 v1(3429,3209) ; J13.25@3482.48,632.01 v1(3482.48,670) ; D35.8@3490,734.44 D35.3@3490,765.56 v1(3490,795) ; v1(3495,1096) 3517.28,1118.28 C82.1@3517.28,1145 C83.1@3517.28,1185 R100.1@3517.28,1230 ; J13.22@3541.54,632.01 v1(3541.54,670) ; J13.19@3600.59,632.01 3600.59,664.59 v1(3610,674) 3620.28,663.72 J13.18@3620.28,632.01 ; v1(3624,3095) D14.3@3624,3130.44 ; D14.8@3624,3161.56 3624,3195 v2(3636,3207) ; v1(3655,2181) 3655,2105 3687.44,2072.56 J2.N1@3701.37,2072.56 ; J13.16@3659.65,632.01 3659.65,663.65 v1(3670,674) ; v1(3701.37,2180) J2.N1@3701.37,2072.56 ; v1(3740,2180) 3740,2100 3712.56,2072.56 J2.N1@3701.37,2072.56 ; v1(3750,675) 3758.07,666.93 J13.11@3758.07,632.01 ; v1(3784,3100) D17.3@3784,3130.44 ; D17.8@3784,3161.56 v1(3784,3187) ; C78.1@3812.28,755 v1(3812.28,782) ; v1(3896,2632) 3912.4,2632 J26.55@3963.2,2682.8 3963.2,2673.8 3967,2670 3967,2620 3959,2612 v1(3959,2609) ; D34.8@3930,729.44 D34.3@3930,760.56 v1(3930,790) ; v1(3945,995) 3970.56,969.44 C81.1@3980,969.44 ; R102.1@3977,1248.54 v1(4003,1248.54) ; C84.1@3980,1136.56 v1(4010,1136.56) ; v1(3995,3180) 4022.72,3152.28 R45.1@4022.72,3142 ; R101.1@4029.52,1248.54 4029.52,1260.52 4036.5,1267.5 v1(4036.5,1274.52) ; v1(4038.43,3671.57) J3.13@4083.46,3671.57 ; v1(4048,612) 4048,564.65 J13.41@4021.85,538.5 4047.5,538.5 4085,576 v1(4085,614) ; v1(4072,846) C53.2@4072,874.44 v1(4102,874.44) ; v1(4083.46,3606.54) J3.13@4083.46,3671.57 ; v1(4083.46,3731.54) J3.13@4083.46,3671.57 ; v1(4118.9,3246.1) J3.11@4118.9,3289.69 ; v1(4118.9,3336.1) J3.11@4118.9,3289.69 ; v1(4130,1180) C126.1@4157.28,1180 ; v1(4130,1220) C128.1@4157.28,1220 ; v1(4130,1255) C121.1@4157.28,1255 ; v1(4140,1990) 4150,1990 4165,1975 C45.1@4172.44,1975 4200,1947.44 v1(4200,1941) ; v1(4151,1362) 4153.63,1359.37 4166.35,1359.37 4168.67,1357.05 4171.42,1357.05 4179.33,1349.14 4179.33,1346.39 C120.1@4193,1332.72 ; D15.2@4151.9,3138 v1(4151.9,3165) ; C122.1@4155,1332.72 4143.33,1344.39 4143.33,1348.72 4136.01,1356.05 4126.67,1356.05 4126.67,1363 v1(4103,1363) 4104,1364 4136.28,1364 C127.1@4157.28,1385 ; v1(4161,1799) 4161,1784.44 C54.1@4182.44,1763 ; v1(4169.69,3289.69) J3.11@4118.9,3289.69 ; C44.1@4172.44,1907 4173,1907.56 v1(4173,1941) ; v1(4185,1792) 4202.28,1809.28 C56.1@4202.28,1810 ; R208.1@4195,1021.72 v1(4218.28,1021.72) ; v1(4217.2,2653) J26.43@4217.2,2706.4 ; v1(4230,842.83) U18.33@4270.59,842.83 ; v1(4231.3,913.7) U18.31@4270.59,913.7 ; v1(4233,2151) 4285.72,2151 4294,2142.72 C48.1@4295,2142.72 ; v1(4245,2325) 4264.4,2344.4 J26.40@4264.4,2383.6 ; D3.3@4249,3119.44 D3.8@4249,3150.56 v1(4249,3178) ; v1(4279,537) 4305.9,537 D25.1@4325,556.1 ; v1(4311.6,2652) J26.37@4311.6,2706.4 4311.6,2743.6 v1(4327,2759) 4343.2,2742.8 J26.35@4343.2,2706.4 ; v1(4320,2445) 4343.9,2445 4358.9,2430 J26.34@4358.9,2383.6 ; v1(4340,3112) 4345.9,3106.1 D2.1@4365,3106.1 ; v1(4376,531) D26.1@4376,556.1 ; v1(4388,3085) 4390.44,3087.44 C31.1@4415,3087.44 4426.72,3075.72 4426.72,3073.28 v1(4445,3055) ; U18.36@4388.7,795.59 4388.7,768.3 v1(4408,749) ; U18.20@4388.7,1244.41 v1(4388.7,1281.3) ; v1(4390,1545) 4407.72,1545 C61.1@4415,1552.28 ; v1(4395,2170) 4395,2167.72 C55.1@4420,2142.72 ; v1(4412,3027) 4420,3019 4420,2972.56 C248.1@4460,2932.56 ; J26.29@4437.6,2706.4 v1(4437.6,2762.6) ; C190.1@4465,2237.44 4465,2207 v1(4478,2194) ; J26.27@4469.1,2706.4 v1(4469.1,2762.1) ; J26.26@4484.9,2383.6 v1(4484.9,2455) ; D4.3@4505,3119.44 D4.8@4505,3150.56 v1(4505,3180) ; J3.6@4516.54,3262.13 v1(4516.54,3325) ; C195.1@4525,2237.44 4525,2225 v1(4540,2210) ; C62.1@4535,2142.72 4535,2160 v1(4545,2170) ; C60.1@4555,1552.28 4572.72,1552.28 v1(4580,1545) ; J26.21@4563.6,2706.4 4563.6,2644 4578.6,2629 v1(4602,2629) ; v1(4570,2210) C202.1@4570,2247.28 ; R73.2@4575,2142.72 v1(4575,2170) ; v1(4590,750) 4602.72,737.28 R201.2@4602.72,715 ; v1(4594,2440) 4610.9,2423.1 J26.18@4610.9,2383.6 ; v1(4605,2820) 4607,2820 4617,2810 C71.1@4627.28,2810 ; C58.1@4615,2142.72 v1(4615,2170) ; C49.1@4645,1607.72 4657.72,1607.72 v1(4705,1655) ; v1(4654.25,3697.14) 4668.14,3697.14 J3.12@4693.7,3671.57 v1(4693.7,3748.7) ; v1(4665,2170) 4665,2139.56 C50.1@4667,2137.56 ; v1(4693.7,3245) J3.10@4693.7,3289.69 v1(4693.7,3331.3) ; U18.3@4719.41,913.7 4745.7,913.7 v1(4755,923) ; U11.2@4735,3115 4767,3115 4796,3144 v1(4796,3149) ; v1(4744,534) D23.1@4744,561.1 ; XT1.2@4744.57,1512.76 4759.57,1497.76 4759.57,1475 v1(4760,1475) ; v1(4765,1159) 4766,1160 4830,1160 4882.72,1212.72 C114.2@4882.72,1220 v1(4910,1220) 4939.24,1249.24 XT2.2@4939.24,1288.57 4981,1330.32 4981,1385 4966,1400 4810,1400 4795,1385 v1(4795,1360) ; v1(4780,1775) 4795,1775 4817.72,1752.28 C57.1@4817.72,1745 ; J26.15@4784.1,2706.4 4784.1,2743.1 v1(4806,2765) ; v1(4785,925) 4796.28,913.72 C115.1@4810,913.72 4823.72,913.72 v1(4835,925) ; v1(4795,535) D22.1@4795,561.1 ; C117.1@4795,1327.72 v1(4795,1360) ; v1(4807,1881) 4807,1878 4817.72,1867.28 C59.1@4817.72,1860 ; XT2.4@4844.76,1359.43 4795.57,1359.43 v1(4795,1360) ; J26.9@4878.6,2706.4 v1(4878.6,2763.6) ; v1(4890,3213) D28.1@4890,3236.1 ; v1(4910,925) 4922.28,912.72 C116.1@4935,912.72 4947.72,912.72 v1(4960,925) ; C209.1@4930,2237.44 4939.84,2247.28 C199.1@4975,2247.28 C200.1@5014,2247.28 ; J26.4@4957.3,2383.6 4957.3,2341.7 v1(4974,2325) ; U11.11@4975,2915 5005,2915 v1(5028,2892) ; U11.15@4975,3115 v1(5025,3115) ; v1(5030,3215) 5040,3225 D27.1@5040,3236.1 ; v1(5040,1430) 5110,1360 5140.31,1360 5140.31,1392.68 v1(5058,1475) ; v1(5048,3448) 5066.1,3429.9 D71.2@5066.1,3425 ; v1(5070,3215) 5080,3225 R81.2@5080,3237.28 ; v1(5099,2835) 5107.72,2843.72 C68.1@5107.72,2860 ; v1(5102.72,3315) C182.1@5102.72,3340 ; v1(5115,3050) 5127.56,3037.44 C249.1@5127.56,3015 C252.1@5127.56,2960 ; J26.56@5116.8,2682.8 5116.8,2698.8 5152,2734 v1(5152,2760) ; C123.1@5117.28,1780 5117.28,1757.72 v1(5120,1755) ; v1(5145,1125) R60.1@5165,1105 ; v1(5152,2785) 5170,2785 5180,2795 D97.1@5206.1,2795 5208.28,2792.82 C66.1@5208.28,2750 ; v1(5158,917) 5166.1,917 5197,886.1 D18.1@5215,886.1 ; J5.H2@5159.92,3616.61 5183.54,3592.99 J5.A12@5198.11,3592.99 ; R60.1@5165,1104.72 R60.1@5165,1105 ; v1(5170,1125) 5165,1120 R60.1@5165,1105 ; v1(5204,2555) 5204,2570.72 C76.2@5212.28,2579 ; v1(5207,2617) 5212.28,2622.28 C77.2@5212.28,2638 ; v1(5207.99,2505) 5207.99,2530.72 C74.2@5212.28,2535 ; v1(5212.28,2445) C73.2@5212.28,2470 ; D9.1@5227,3481.1 5227,3470 5233,3464 v1(5233,3455.32) ; v1(5235,1193) 5238,1190 D65.2@5297.1,1190 ; v1(5259.45,3460.55) D10.1@5280,3481.1 ; D20.1@5265,886.1 5273.1,886.1 v1(5286,899) ; D30.1@5328.9,2470 v1(5355,2470) ; D31.1@5328.9,2535 5354.89,2535 v1(5355,2534.89) ; D32.1@5328.9,2579 v1(5354,2579) ; D33.1@5328.9,2638 5343,2638 v1(5355,2650) ; v1(5330,3456) D12.1@5330,3481.1 ; C65.1@5334.72,2755 v1(5360,2755) 5367,2748 5367,2723.72 C63.2@5364,2720.72 ; D29.1@5335.9,2795 v1(5360,2795) ; J5.A1@5461.89,3592.99 5476.46,3592.99 J5.H1@5500.08,3616.61 ; v1(5474,3431) C32.1@5474,3462.44 v1(5505,3462.44)
  TOP w20: v1(1351,1197.72) C89.1@1375,1197.72 v1(1395,1197.72) C88.1@1417,1197.72 ; v1(1455,973) U13.2@1455,1006.85 ; 3025,3495 3025.08,3494.92 J14.20@3067.6,3494.92 ; R72.1@4695,692.72 4706.28,692.72 v1(4724,675)
  TOP w24: 3160,3595 LED1.2@3195,3595 ; 3195,3560 LED1.2@3195,3595 ; 3195,3630 LED1.2@3195,3595 ; 3230,3595 LED1.2@3195,3595
  TOP w35: 458.67,1605.08 J16.6@491.26,1605.08 523.85,1605.08 ; 458.67,1920.04 J16.14@491.26,1920.04 523.85,1920.04 ; 458.67,2767.44 J28.14@491.26,2767.44 523.85,2767.44 ; 537.41,1605.08 J16.5@570,1605.08 602.59,1605.08 ; 629.95,2191 H2.1@759,2191 ; 759,2061.95 H2.1@759,2191 ; 759,2320.05 H2.1@759,2191 ; 1005,3198 J22.10@1005,3235 ; 1005,3272 J22.10@1005,3235 ; 1042,3235 J22.10@1005,3235 ; 1745,3198 J23.10@1745,3235 ; 1745,3272 J23.10@1745,3235 ; 1782,3235 J23.10@1745,3235 ; 2496.73,3428.86 J14.21@2496.73,3494.92 ; 2496.73,3560.98 J14.21@2496.73,3494.92 ; 2496.73,3683.2 J14.22@2496.73,3729.57 ; 2496.73,3775.94 J14.22@2496.73,3729.57 ; 2527.35,3494.92 J14.21@2496.73,3494.92 ; 2527.35,3729.57 J14.22@2496.73,3729.57 ; 3036.97,3729.57 J14.23@3067.6,3729.57 ; 3067.6,3683.2 J14.23@3067.6,3729.57 ; 3067.6,3775.94 J14.23@3067.6,3729.57 ; 3098.22,3729.57 J14.23@3067.6,3729.57 ; 3374.34,3533.74 J6.21@3436.34,3533.74 3436.34,3595.74 ; 3436.34,3248.12 J6.20@3436.34,3310.12 3498.34,3310.12 ; 3528.2,3455 J6.4@3557.2,3455 ; 3540.83,879.65 J2.N3@3646.26,879.65 ; 3557.2,3484 J6.4@3557.2,3455 ; 3586.2,3455 J6.4@3557.2,3455 ; 3646.26,774.22 J2.N3@3646.26,879.65 ; 3666,3395.94 J6.7@3695,3395.94 ; 3695,3424.94 J6.7@3695,3395.94 ; 3724,3395.94 J6.7@3695,3395.94 ; 3751.69,879.65 J2.N3@3646.26,879.65 ; J27.G4@3760.32,1360 J27.G4@3855.91,1360 J27.G4@3855.91,1455.59 ; 3891.66,3533.74 J6.22@3953.66,3533.74 ; 3953.66,3248.12 J6.19@3953.66,3310.12 3953.66,3372.12 ; 3953.66,3595.74 J6.22@3953.66,3533.74 ; 4015.66,3533.74 J6.22@3953.66,3533.74 ; 4422.49,405 J9.4@4453.11,405 ; 4453.11,435.62 J9.4@4453.11,405 ; 4483.73,405 J9.4@4453.11,405 ; 4856.19,405 J8.4@4886.81,405 ; 4886.81,435.62 J8.4@4886.81,405 ; 4917.43,405 J8.4@4886.81,405 ; 4919.41,655 H1.1@5015,655 ; 5015,559.41 H1.1@5015,655 ; 5015,750.59 H1.1@5015,655 ; 5129.3,3616.61 J5.H2@5159.92,3616.61 5159.92,3672.83 ; 5133.23,3780 J5.H4@5159.92,3780 ; 5159.92,3733.63 J5.H4@5159.92,3780 ; 5186.61,3780 J5.H4@5159.92,3780 ; 5239.38,2984.37 J11.2@5270,2984.37 ; 5270,2953.75 J11.2@5270,2984.37 ; 5289.89,405 J7.4@5320.51,405 5320.51,435.62 ; 5300.62,2984.37 J11.2@5270,2984.37 ; 5409.53,945 J24.33@5450,945 ; 5450,904.53 J24.33@5450,945 ; 5473.39,3780 J5.H3@5500.08,3780 ; 5490.47,945 J24.33@5450,945 ; 5500.08,3672.83 J5.H1@5500.08,3616.61 5530.7,3616.61 ; 5500.08,3733.63 J5.H3@5500.08,3780 ; 5509.53,945 J24.34@5550,945 ; 5509.53,1445 J24.24@5550,1445 ; 5526.77,3780 J5.H3@5500.08,3780 ; 5550,904.53 J24.34@5550,945 ; 5550,985.47 J24.34@5550,945 ; 5550,1404.53 J24.24@5550,1445 ; 5550,1485.47 J24.24@5550,1445 ; 5550,2304.53 J24.6@5550,2345 5550,2385.47
  BOTTOM w5: D79.2@870,2967.9 890.71,2967.9 894.71,2971.9 977.1,2971.9 v1(994.5,2954.5) 1011,2938 1011,2853 1032,2832 ; v1(1071,1936) 1079,1944 1106,1944 1115,1935 1115,1925 1115,1652 1105,1642 1077,1642 v1(1074,1645) ; v1(1187.39,2507.3) 1190.31,2504.38 1190.31,2458.93 1188.67,2457.3 1188.67,2441.28 1188.67,2424.71 1199,2414.38 1199,2063 1160.5,2024.5 1160.5,2005.5 1155,2000 1155,1333 1209,1279 1213.16,1279 v1(1213.37,1278.79) 1218,1278.79 1219.21,1280 v1(1240,1280) 1240,1255 1205,1220 1205,1185 1165,1145 1165,1015 1213,967 1213,847 1272.99,787 1322.99,787 1423,687 1423,607 1425,605 1425,604.29 1494.29,535 1495,535 1497.49,532.5 1652.49,532.5 1765,420 3090,420 3150,480 3883,480 3892,489 3893.5,490.5 4110.35,490.5 4110.85,490.99 4124.99,490.99 4177.96,543.96 4189.67,555.67 4231.88,555.67 4232.21,556 4238.71,556 4244,561.29 4244,567.79 4252.21,576 4258,576 4263,581 4263,657 4240,680 4240,832.83 v1(4230,842.83) 4232,844.83 4232,1008 v1(4218.28,1021.72) 4160,1080 4120,1080 4110,1070 4110,1050 4200,960 4200,810 4220,790 4220,670 4243,647 4243,599.67 4234.33,591 4234.33,586.62 4234.33,586.41 4223.59,575.67 4181.39,575.67 4157.96,552.25 4116.71,511 4102.57,511 4102.07,510.5 3876.5,510.5 3866,500 3137.92,500 3087.92,450 v1(3000,450) v1(2910,450) v1(2710,450) v1(2525,450) v1(2355,450) v1(2210,450) v1(2070,450) v1(1920,450) v1(1780,450) 1765,450 1660,555 1502.57,555 1445,612.57 1445,715 1410.33,749.67 1403.99,749.67 1392.67,760.99 1392.67,767.33 v1(1390,770) 1375,770 1335,810 1285,810 1235,860 1235,980 1190,1025 1190,1140 1235,1185 1235,1215 1270,1250 1270,1307 1245,1332 v1(1235.63,1332) 1235.63,1332.37 1208,1360 v1(1195,1360) 1191,1364 1186,1364 1175,1375 1175,1990 1180.5,1995.5 1180.5,2015.36 1219,2053.86 1219,2422.67 1208.67,2432.99 1208.67,2449.01 1220,2460.33 1220,2461 1223,2464 v1(1223,2468) ; 1270,1919 1264,1925 1264,1948.44 1269,1953.44 1269,1954 1271,1956 1271,1985 1308,2022 1308,2260 1380,2332 1380,2420 1390,2430 1390,2460 1377,2473 v1(1375,2473) 1374.66,2473.34 1363.34,2473.34 1350,2460 1350,2336 1285,2271 1285,2030.76 1244,1989.76 1244,1528 1362,1410 1585.5,1410 1622.17,1446.67 1646.67,1446.67 1720,1520 1720,1540 v1(1765,1585) ; v1(1334,1973) 1335,1972 1335,1925 1316,1925 1285,1894 1277,1886 1277,1525 1365,1437 1577,1437 1615,1475 v1(1622,1475) ; v1(1340,2855) 1380,2815 1387,2815 1388,2814 1626,2814 1670,2770 1670,2578 1651,2559 1651,2516 1489,2354 1489,2285 1421,2217 1421,2124 1470,2075 1470,1835 1531,1774 v1(1531,1765) ; v1(1369,1627) 1369,1616 1364,1611 1364,1563 1376,1551 1391,1551 1408,1568 1417,1568 1434,1585 1705,1585 ; v1(1369.5,1740) 1369.5,1748.5 1360,1758 1360,1790 1380,1810 v1(1389,1810) 1389,1827 1425,1863 1436,1863 v1(1441,1868) ; v1(1435,2505) 1440,2500 1440,2480 1420,2460 1420,2410 1407.5,2397.5 1407.5,2325.5 1339,2257 1339,2086 1365,2060 1365,1905 1314,1854 v1(1314,1853) 1299,1838 1299,1533 1367,1465 1559,1465 1615,1521 1615,1535 1625,1545 1645,1545 1661.84,1528.16 ; v1(1511,2135) 1510,2135 1501,2144 1501,2176 1520,2195 1520,2329 v1(1632,2441) 1638,2441 1681,2484 1681,2543 1700,2562 1700,2801 1657,2844 1439,2844 1410,2873 1332,2873 v1(1320,2885) v1(1290,2885) 1288,2885 1280,2893 1172,2893 1127,2938 1127,2981 1142,2996 1371,2996 v1(1387,2980) 1401,2994 1583,2994 1597,2980 1729,2980 1820,2889 1820,2509 1803,2492 1803,2458 v1(1825,2436) 1835,2446 2263,2446 2278,2431 2316,2431 v2(2320,2435) 2345,2435 2358,2448 v1(2358,2465) ; v1(1610,1825) 1611,1824 1611,1795 1573,1757 1552,1757 1544,1765 v1(1531,1765) ; v1(1627,2582) 1627,2522 1555,2450 v1(1540,2450) 1540,2435 1469,2364 1469,2295 1401,2227 1401,2114 1450,2065 1450,2029 v1(1436,2015) 1450,2001 1450,1877 v1(1441,1868) ; v1(1745,1625) 1745,1655 1784,1694 1784,1738 1799,1753 1799,1940 1819,1960 1836,1960 1848,1948 1893,1948 v1(1900,1955) ; v1(1814,885) 1820,879 1854,879 1875,900 2005,900 2030.67,874.33 2154.67,874.33 2159.67,869.33 2159.67,857.99 2170.99,846.67 2187.01,846.67 2198.33,857.99 2198.33,869.33 2203.33,874.33 2319.33,874.33 2345,900 2345,944 v1(2355,954) 2355,854 2336,835 1954,835 v1(1945,844) 1945,858 1935,868 1900,868 1878,846 1832,846 1821,835 1821,764 1835,750 1860,750 1915,695 2006,695 v1(2015,686) ; v1(1815,955) 1850,955 1875,930 2020,930 2046,904 2304,904 2315,915 2315,970.86 2331,986.86 2331,1040 2340,1040 v1(2360,1060) 2365,1060 2510,1205 2967.28,1205 3025.28,1205 3032,1205 3345,1518 3345,1555 3375,1585 3443,1585 3483,1625 3629,1625 3755,1751 3849,1751 3864,1736 v1(3912,1736) ; v1(1885.5,838.5) 1891.5,838.5 1915,815 2370,815 v1(2380,825) 2380,935 2400,955 2400,987 v1(2395,992) 2395,1000 2405,1010 2405,1055 2525,1175 3044,1175 3385,1516 3385,1535 v1(3390,1540) 3405,1555 3455,1555 3495,1595 3641,1595 3766,1720 3835,1720 3851,1704 v1(3851,1685) ; v1(1901,2170) 1905,2170 1922,2153 1997,2153 2015,2135 2246.71,2135 2318.73,2207.01 2343.58,2207.01 2356.01,2207.01 2368.43,2207.01 2376.71,2207 2424,2207 2505,2126 2811,2126 2835,2150 2835,2800 2935,2900 2945,2900 v1(2952,2907) 2953,2907 2964.67,2918.67 2964.67,2919.67 2966.5,2921.5 2967.5,2921.5 v1(2968,2922) 2968,2923 2979,2934 2980,2934 v1(2983.5,2937.5) 2986,2935 2993,2935 3014,2956 3037,2956 3056,2975 3569,2975 3639,2905 3980,2905 4021,2946 4099,2946 4128,2975 4245.86,2975 4248.86,2978 4249.71,2978 4251.39,2979.67 4251.59,2979.67 4253.92,2982 4436.08,2982 4436.41,2981.67 4451.59,2981.67 4451.92,2982 4454,2982 4465,2993 4465,3040 4450,3055 v1(4445,3055) 4429,3039 4424,3039 v1(4412,3027) 4397,3012 4290,3012 4248,3054 4116,3054 4107,3045 4077,3045 v1(4076,3046) ; v1(1902,2130) 1911.67,2120.33 1916.84,2120.33 1921.51,2125 1928.84,2132.33 1977.16,2132.33 1994.49,2115 2255,2115 2327.01,2187.01 2335.29,2187.01 2347.72,2187.01 2360.14,2187.01 2368.42,2187 2415.71,2187 2497.71,2105 2820,2105 2856,2141 2856,2330 v1(2865.71,2339.71) 2865.29,2339.71 2855,2350 2855,2780 2921,2846 2934,2846 3023,2935 3046,2935 3066,2955 3559,2955 3630,2884 3989,2884 4031,2926 4109,2926 4138,2955 4255,2955 4260,2960 4462,2960 4485,2983 4485,3010 4490,3015 4490,3075 v1(4476,3089) ; v1(1915,1975) 1915,1978 1856,2037 1856,2194 1920.5,2258.5 2007.5,2258.5 2061,2205 2193.59,2205 2212.32,2223.74 2238.24,2223.74 v1(2254.85,2240.34) ; v1(1958.99,1173.99) 1967.98,1165 1987,1165 2040,1218 2040,1316 2027,1329 v1(2003,1329) ; v1(2279.25,2264.75) 2279.75,2264.75 2301,2286 2301,2307.59 2311.73,2318.33 2326.92,2318.33 2330.12,2315.12 2339,2324 ; v1(2341,1204) 2349,1204 2410,1265 2416.28,1265 2441.14,1265.01 2463.71,1265 2992.14,1265 3000.43,1265 3180,1444.57 3180,1480 3389,1689 3621,1689 3629,1681 3650,1681 v1(3666,1697) 3666,1698 3644,1720 3615,1720 3605,1710 3380,1710 3158,1488 3158,1450.86 2992.14,1285 2472,1285 2449.43,1285 2408.01,1285.01 2384,1285 v1(2341,1242) ; v1(2506,1791) 2510,1795 2625,1795 ; v1(2523,1035) 2523,967 2537,953 v1(2537,942) 2536,941 2536,908 2545,899 ; v1(2559,1766) 2568,1775 2893,1775 v1(2909,1791) ; v1(2570,1610) 2585,1610 2615,1640 2685,1640 2725,1680 2725,1705 2755,1735 2965,1735 3014.5,1784.5 v1(3014.5,1810.5) 3014.5,1859.5 3115,1960 3115,2280 v1(3160,2325) 3160,2340 3210,2390 3210,2619 3262,2671 3278,2671 3288,2661 3288,2643 3230,2585 3230,2380 3201,2351 v1(3201,2326) 3195,2320 3195,2310 3135,2250 3135,1887 3045,1797 3045,1785 2975,1715 2765,1715 2745,1695 2745,1670 2685,1610 v1(2684,1610) 2660,1610 2656,1606 v1(2641,1606) ; v1(2580,2214) 2564,2198 2532,2198 2452,2278 2348,2278 2339,2287 2339,2324 ; v1(2605,1815) 2625,1795 ; v1(2716,2214) 2739,2237 2739,2382 2690,2431 2690,2515 2590,2615 2326,2615 2323,2618 ; v1(2740,945) 2750,945 2810,1005 3085,1005 3438,1358 v1(3455,1358) ; v1(2794,946) 2833,985 3095,985 3425,1315 3455,1315 3495,1355 v1(3495,1365) ; v1(2847,3220) 2871.92,3220 2907,3255.08 2907,3295.1 v1(2932,3320.1) 2955.9,3344 3013,3344 v1(3023,3354) 3033,3344 3157,3344 v1(3166,3353) 3173,3360 3315,3360 ; v1(2914,2656) 2914,2657 2911,2660 2911,2720 ; v1(3055,3044) 3059,3044 3066,3037 3137,3037 v1(3144,3044) ; v1(3129,2795) 3115,2781 3115,2720 3099,2704 3099,2604 3055,2560 3055,2425 3035,2405 3035,2005 2925,1895 2925,1849 2871,1795 2625,1795 ; v1(3167,2790) 3160,2783 3160,2765 3135,2740 3135,2710 3119,2694 3119,2594 3075,2550 3075,2444 v1(3084,2435) ; v1(3430,2330) 3435,2325 v1(3435,2200) 3504.28,2200 3649.28,2055 3958,2055 3963,2050 v1(3963,2043) ; C112.1@3461,2524.28 3440.74,2524.28 3400,2565.02 3400,2650 v1(3404,2654) 3427,2654 3440.5,2640.5 3440.5,2624.5 3520,2545 3520,2214.28 3659.28,2075 4026,2075 v1(4029.5,2071.5) ; J6.13@3557.2,3329.02 3538.3,3310.12 J6.20@3436.34,3310.12 3358.88,3310.12 3358.88,3316.12 3322,3353 ; v1(3564.5,2654.5) 3564.5,2640.5 3625,2580 3625,2370 3580,2325 3580,2245 3644,2181 v1(3655,2181) 3655,2170 3670,2155 3992,2155 4018,2129 v1(4018,2139) ; v1(3924,2825) 3916,2817 3774,2817 3757,2834 3604,2834 3533,2905 3090,2905 3059,2874 v1(3047,2874) 3046,2874 3012,2840 3002,2840 2911,2749 2911,2720 ; v1(3979,2825) 4004,2825 4054,2875 4300,2875 4335,2910 4505,2910 4635,3040 4715,3040 4750,3075 4963.59,3075 5069,2969.59 5069,2821 5081,2809 5081,2644 5175,2550 5175,2482.28 v1(5212.28,2445) 5270,2387.28 5270,2253 v1(5260,2243) 5260,2249 5230,2279 5230,2300 5250,2320 5250,2365 5155,2460 5155,2540.86 5057,2638.86 5057,2801 5042,2816 ; v1(4016,3046) 3945,2975 3677,2975 3607,3045 3311,3045 3273,3083 3273,3095 3256.5,3111.5 3014.58,3111.5 2703.33,2800.25 2701.25,2800.25 2701,2800 2505,2800 v1(2490,2785) 2485,2780 2469,2780 2346,2657 2346,2641 2323,2618 ; v1(4806,2765) 4806,2768 4772,2802 4772,2875 4784,2887 v1(4784,2890) 4811,2890 v1(4824,2877) 4814,2867 4814,2799 4849,2764 4878.2,2764 v1(4878.6,2763.6) 4878.6,2736.4 4893,2722 4893,2633 4845,2585 4845,2482 4839,2476 4858,2457 4864,2457 4878,2443 4878,2427 4868,2417 4847,2417 ; 4836,2609 4859,2632 v1(4859,2648) ; v1(5028,2892) 5030,2892 5049,2911 5049,2960 4955,3054 4763,3054 4729,3020 4644.14,3020 4514.14,2890 4345,2890 4310,2855 4064,2855 4005,2796 3765,2796 3747,2814 3693.5,2814 v1(3684,2804.5) 3603.5,2804.5 3541,2867 3518,2867 v1(3509,2876) 3500,2885 3100,2885 3030,2815 3008,2815 2975.04,2782.04 2975.04,2772.88 2977.81,2770.11 2977.81,2768.76 2979.51,2767.05 2979.51,2758.49 2984,2754 2984,2734 2970,2720 2911,2720 ; v1(1441,1868) 1450,1859 1450,1800 1495,1755 1521,1755 v1(1531,1765) ; 2323,2618 2309,2604 v1(2263,2604) 2262,2605 v1(2213,2605) v1(2157,2605) v1(2105,2605) 2103,2607 v1(2046,2607) 2036,2597 1996,2597 1987,2606 v1(1987,2608) 1988,2609 v1(1988,2659) 1988,2720 2019,2751 2019,2874 2058,2913 2179,2913 2224,2958 2224,3013 2188,3049 2007,3049 1951,2993 1818,2993 1797,2972 1797,2943 1845,2895 1845,2562 1928,2479 2331.99,2479 2335.5,2475.5 2352.5,2475.5 2375,2498 2513,2498 2525,2486 v1(2525,2472) 2525,2436 v1(2523,2434) 2493,2404 2493,2364 2479,2350 2355,2350 2339,2334 2339,2324 ; v1(2909,1791) 2916.5,1798.5 2916.5,1803.5 2945,1832 2945,1882.62 3055,1992.62 3055,2390 3084,2419 v1(3084,2435) ; v1(2909,1791) 2910,1791 2925,1776 2946,1776 2965,1795 2965,1870 3075,1980 3075,2365 3135,2425 3135,2445 3125,2455 3104,2455 v1(3084,2435) ; 3315,3360 3322,3353 ; 3315,3360 3322,3353
  BOTTOM w8: v1(884.41,1588.25) 888,1588.25 888.25,1588 892,1588 893.58,1586.42 v1(911,1586.42) 973.58,1586.42 ; v1(1375,2473) 1391,2489 v1(1391,2510) ; v1(1622,1475) 1622,1477 1661.84,1516.84 ; v1(1662,1300) 1680,1282 1680,854 1673,847 v1(1671,847) 1666,842 1666,641 1716.5,590.5 v1(1716.5,585.5) 1722.5,585.5 1797,511 3066,511 3343,788 3343,898 v1(3350,905) 3344,911 3344,954 3486,1096 v1(3495,1096) 3495,1105 3681,1291 v1(3695,1291) 3697.49,1293.49 3697.49,1307.49 3720,1330 3720,1343 v1(3716,1347) 3720,1351 3720,1365 3763.5,1408.5 3763.5,1436 3771.5,1444 v1(3773,1444) 3779,1450 3805,1450 3835,1480 3909,1480 v1(3925,1464) ; v1(1695,1360) 1699,1356 1699,1333 1721,1311 1721,821 1707,807 1707,665 1778.5,593.5 v1(1787.5,593.5) 1826,555 3050,555 3295,800 v1(3295,905) v1(3295,945) 3295,965 3665,1335 3665,1370 3722,1427 3722,1462 3752,1492 3787,1492 3820,1525 4031,1525 4113,1607 4257,1607 4285,1635 4615,1635 4715,1735 4735,1735 4775,1775 v1(4780,1775) 4820,1815 5260,1815 5320,1875 5320,2175 5355,2210 v1(5355,2255) v1(5355,2304) v1(5355,2470) ; v1(1765,1585) 1775,1585 1865,1675 1865,1745 1887.48,1767.48 J27.G2@1922.84,1767.48 1900,1790.32 1900,1806 1919,1825 1989,1825 v1(1999,1815) 2004,1810 2040,1810 2052.5,1822.5 2052.5,1847.5 2045,1855 1906,1855 v1(1894,1843) 1893,1843 1888,1843 1840,1795 1840,1690 1775,1625 v1(1745,1625) 1705,1585 1685,1565 1685,1540 1673.16,1528.16 ; v1(1780,1360) 1780,1352.84 1779.83,1352.66 1779.83,1331.79 1776.5,1328.46 1776.5,1326.5 1775,1325 1775,795 1761,781 1761,689 1794,656 1811,656 1857,610 2305,610 v1(2315,620) 2324.34,610.66 2335.66,610.66 v1(2345,620) 2354.34,610.66 2365.66,610.66 v1(2375,620) 2384.34,610.66 2395.66,610.66 v1(2405,620) 2415,610 3020,610 3230,820 3230,930 3216,944 ; v1(3197,944) 3216,944 ; v1(3916,1615) 3916,1591 3905,1580 3844,1580 3838,1586 v1(3802,1586) 3769,1553 v1(3736,1553) 3733,1550 3725,1550 3666,1491 v1(3664,1491) 3664,1490 3670,1484 3670,1460 3654,1444 v1(3637,1444) 3637,1422 3620,1405 v1(3600,1405) 3601,1404 v1(3601,1371) 3601,1351 3255,1005 v1(3245,1005) 3245,995 3230,980 3230,952 3222,944 3216,944 ; v1(3954,1659) 3971,1676 4248,1676 4265,1693 4593,1693 4700.8,1800.8 4709.8,1800.8 v1(4710.8,1801.8) 4710.8,1810.8 4781,1881 v1(4807,1881) 4808,1880 4815,1880 4874,1880 v1(4879,1885) 4891,1873 5238,1873 5265,1900 5265,2200 5293.51,2228.51 5293.51,2476.49 5285,2485 ; v1(4138,1547) 4140,1547 4157.83,1564.83 4250.17,1564.83 4261,1554 4264,1554 4305,1595 4635,1595 4695,1655 v1(4705,1655) 4705,1664 4728.5,1687.5 4759.5,1687.5 4842,1770 5105,1770 v1(5120,1755) 5135,1770 5275,1770 5365,1860 5365,2160 5405,2200 5405,2670 5360,2715 v1(5360,2755) ; v1(4796,3149) 4789,3142 4721,3142 4694,3115 4645,3115 4610,3150 4560,3150 4550,3140 4550,3080 4566,3064 4705,3064 4738,3097 4972,3097 5099,2970 v1(5099,2835) 5105,2829 5105,2652 5202,2555 v1(5204,2555) 5204,2551 5210,2545 5210,2507.01 v1(5207.99,2505) 5207.99,2501.01 5224,2485 5285,2485 ; 5085,3115 5123,3153 5150,3153 5198,3105 5198,3008 5175,2985 5175,2830 5198,2807 5198,2703 5293,2608 5293,2493 5285,2485 ; v1(5152,2785) v1(5152,2760) 5152,2672 v1(5207,2617) ; 5265,2815 5250,2800 5250,2730 5330,2650 v1(5355,2650) ; 1661.84,1516.84 1661.84,1528.16 1673.16,1528.16 ; 1661.84,1516.84 1673.16,1528.16
  BOTTOM w10: v1(750,2470) 712,2432 621,2432 606,2447 606,2471 585,2492 463,2492 440,2515 440,2716 491.26,2767.26 J28.14@491.26,2767.44 439.5,2819.2 439.5,3004.5 477,3042 698,3042 768.1,2971.9 842.79,2971.9 846.79,2967.9 D79.2@870,2967.9 ; v1(947,2461) 965,2479 1060,2479 1137,2556 v1(1137,2605) 1126,2616 1097,2616 v1(1070,2643) 1070,2672 1023,2719 1023,2721 v1(991,2753) 1010,2772 1010,2810 1032,2832 ; J15.18@1027.99,1625.79 988.79,1625.79 981.68,1618.68 972.19,1618.68 967.69,1614.17 945.3,1614.17 941.13,1610 904,1610 881,1633 757,1633 713,1677 v1(713,1695) 686,1722 v1(686,1749) 672,1763 672,1819 v1(680,1827) 666,1841 666,1899 v1(680,1913) 727,1960 775,1960 v1(777,1958) 794,1975 859.28,1975 C260.1@929.28,2045 943,2031.28 943,1991 959,1975 970,1975 980,1965 v1(984,1965) 984,1953 996.25,1940.75 J15.34@1027.99,1940.75 ; v1(1700,2100) 1706,2106 1706,2296 1825,2415 v1(1825,2436) ; v1(2015,686) 2062,733 2415,733 2430,748 2650,748 2660,758 v1(2660,802) 2660,850 2635,875 2569,875 2545,899 ; v1(4796,3149) 4796,3140 5000,3140 v1(5025,3115) ; 5085,3115 5085,3080 v1(5115,3050)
